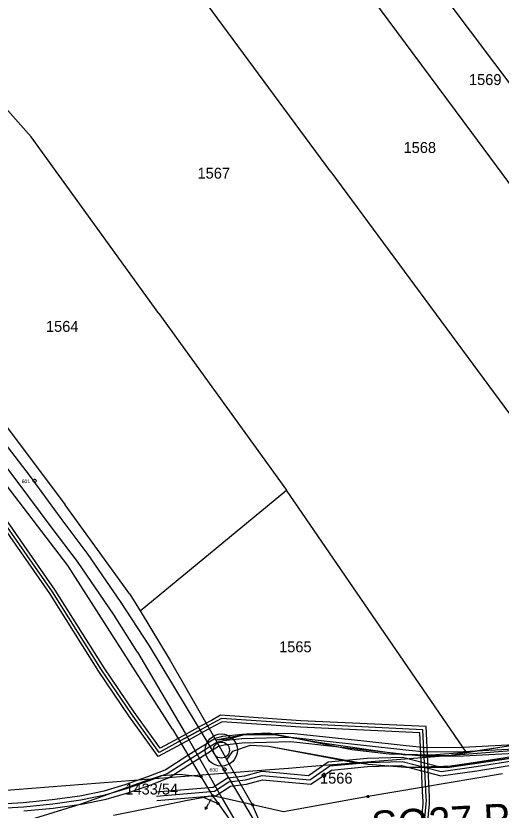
# Model space of a CAD drawing. Extents: x -510185 to -506993, y -1126306 to -1123642.
# Drawn here: x -509243.9 to -509017.3, y -1126120.6 to -1125749.7 of the extents above; entities that cross this region are included whole.
import ezdxf

# ---------------------------------------------------------------- set-up
doc = ezdxf.new("R2010")
doc.units = 0
for name, color, linetype in [('návrh', 7, 'Continuous'), ('ochranná pásma', 7, 'Continuous'), ('parcelni hranice', 7, 'Continuous'), ('telefonica', 7, 'Continuous'), ('u_kabely', 7, 'Continuous'), ('u_Telefonica', 7, 'Continuous'), ('u_Telematika', 7, 'Continuous'), ('u_teliasonera', 7, 'Continuous'), ('u_vysadba_oseti', 7, 'Continuous'), ('ˇ2', 7, 'Continuous'), ('ˇ3', 7, 'Continuous'), ('ˇ4', 7, 'Continuous'), ('ˇ7', 7, 'Continuous'), ('ˇ8', 7, 'Continuous')]:
    doc.layers.add(name, color=color, linetype=linetype)

msp = doc.modelspace()

# ---------------------------------------------------------------- linework, layer by layer
at = {"layer": 'návrh'}
for radius in [7.5, 3.75]:
    msp.add_circle((-509147.97, -1126092.6), radius, dxfattribs=at)
at = {"layer": 'ochranná pásma'}
for p, q in [((-509105.94, -1126100.2), (-508824.34, -1126077.96)), ((-509299.93, -1126115.29), (-509125.3, -1126101.71)), ((-509125.3, -1126101.71), (-509116.65, -1126101.04)), ((-509116.65, -1126101.04), (-509105.94, -1126100.2))]:
    msp.add_line(p, q, dxfattribs=at)
at = {"layer": 'parcelni hranice'}
for p, q in [((-509132.45, -1125667.17), (-509031.17, -1125804.26)), ((-509096.96, -1125670.04), (-508984.48, -1125819.86)), ((-509096.82, -1125822.54), (-509195.52, -1125688.71)), ((-509270.54, -1125768.18), (-509236.85, -1125806.19)), ((-509031.17, -1125804.26), (-508929.89, -1125941.34)), ((-509177.23, -1125888.69), (-509236.85, -1125806.19)), ((-509096.82, -1125822.54), (-508998.12, -1125956.36)), ((-509177.23, -1125888.69), (-509117.61, -1125971.19)), ((-509219.69, -1126006.46), (-509290.67, -1125913.76)), ((-509253.29, -1125935.06), (-509220.87, -1125978.05)), ((-509185.92, -1126027.53), (-509117.61, -1125971.19)), ((-509033.47, -1126093.73), (-509117.61, -1125971.19)), ((-509190.65, -1126019.76), (-509220.87, -1125978.05)), ((-509170.84, -1126082.86), (-509219.69, -1126006.46)), ((-509190.65, -1126019.76), (-509185.92, -1126027.53)), ((-509185.92, -1126027.53), (-509171.81, -1126050.71)), ((-509171.81, -1126050.71), (-509150.59, -1126088)), ((-509170.84, -1126082.86), (-509157.49, -1126104.93)), ((-509144.61, -1126087.44), (-509150.59, -1126088)), ((-509136.24, -1126085.24), (-509144.61, -1126087.44)), ((-509125.75, -1126084.77), (-509136.24, -1126085.24)), ((-509087.06, -1126092.49), (-509125.75, -1126084.77)), ((-509150.59, -1126088), (-509145.35, -1126097.2)), ((-509142.58, -1126093.06), (-509134.29, -1126090.27)), ((-509134.29, -1126090.27), (-509125.88, -1126090.73)), ((-509125.88, -1126090.73), (-509088.21, -1126097.98)), ((-509000.11, -1126088.82), (-509033.47, -1126093.73)), ((-509145.35, -1126097.2), (-509142.58, -1126093.06)), ((-509069.53, -1126094.45), (-509087.06, -1126092.49)), ((-509049.74, -1126094.93), (-509069.53, -1126094.45)), ((-509033.47, -1126093.73), (-509049.74, -1126094.93)), ((-509133.41, -1126118.18), (-509145.35, -1126097.2)), ((-509088.21, -1126097.98), (-509079.38, -1126099.22)), ((-509038.29, -1126099.96), (-509009.46, -1126095.8)), ((-509079.38, -1126099.22), (-509061.84, -1126100.54)), ((-509061.84, -1126100.54), (-509038.29, -1126099.96)), ((-509184.36, -1126107.35), (-509175.99, -1126104.45)), ((-509175.99, -1126104.45), (-509167.34, -1126103.9)), ((-509167.34, -1126103.9), (-509157.49, -1126104.93)), ((-509157.49, -1126104.93), (-509152.05, -1126113.93)), ((-509016.64, -1126103.65), (-509079.41, -1126114.29)), ((-509213.38, -1126117.64), (-509184.36, -1126107.35)), ((-509164.5, -1126116.32), (-509180.44, -1126119.53)), ((-509156.22, -1126114.73), (-509164.5, -1126116.32)), ((-509152.05, -1126113.93), (-509156.22, -1126114.73)), ((-509156.22, -1126114.73), (-509149.48, -1126117.53)), ((-509152.05, -1126113.93), (-509149.48, -1126117.53)), ((-509147.69, -1126114.92), (-509152.05, -1126113.93)), ((-509137.41, -1126117.27), (-509147.69, -1126114.92)), ((-509079.41, -1126114.29), (-509118.98, -1126121.47)), ((-509248.18, -1126128.53), (-509213.38, -1126117.64)), ((-509180.44, -1126119.53), (-509198.31, -1126123.18)), ((-509149.48, -1126117.53), (-509131.41, -1126142.82)), ((-509133.41, -1126118.18), (-509137.41, -1126117.27)), ((-509123.08, -1126141.76), (-509133.41, -1126118.18)), ((-509118.98, -1126121.47), (-509133.41, -1126118.18))]:
    msp.add_line(p, q, dxfattribs=at)
at = {"layer": 'telefonica'}
for points in [[(-509188.65, -1126074.91), (-509202.69, -1126054.24), (-509225.62, -1126017.86), (-509249.3, -1125983.88), (-509275.16, -1125949.5), (-509300.47, -1125915.43), (-509336.7, -1125871.25)], [(-509191.13, -1126076.6), (-509205.2, -1126055.89), (-509228.12, -1126019.51), (-509251.73, -1125985.64), (-509277.57, -1125951.3), (-509302.83, -1125917.28), (-509339.02, -1125873.16)], [(-509152.64, -1126078.73), (-509157.74, -1126081.5), (-509165.82, -1126085.91), (-509176.52, -1126091.75), (-509188.68, -1126074.88)], [(-509110.81, -1126078.92), (-509148.31, -1126076.36), (-509152.64, -1126078.73)], [(-509151.21, -1126081.36), (-509156.3, -1126084.14), (-509164.39, -1126088.55), (-509177.41, -1126095.65), (-509191.11, -1126076.63)], [(-509111.02, -1126081.92), (-509147.64, -1126079.41), (-509151.21, -1126081.36)], [(-509035.07, -1126146.08), (-509047.88, -1126145.88), (-509052.14, -1126132.19), (-509050.74, -1126117.76), (-509050.68, -1126116.1), (-509050.8, -1126114.54), (-509052.36, -1126081.64), (-509110.85, -1126078.92)], [(-509037.56, -1126149.04), (-509050.1, -1126148.85), (-509055.18, -1126132.5), (-509053.73, -1126117.56), (-509053.69, -1126116.16), (-509053.79, -1126114.72), (-509055.23, -1126084.51), (-509110.99, -1126081.92)]]:
    msp.add_lwpolyline(points, dxfattribs=at)
at = {"layer": 'u_kabely'}
for points in [[(-509264.3, -1126118.51), (-509240.59, -1126117.08), (-509226.95, -1126115.72), (-509214, -1126113.93), (-509202.75, -1126111.6), (-509192.89, -1126108.72), (-509181.81, -1126104.87), (-509174.17, -1126101.82), (-509163.64, -1126095.05), (-509159.85, -1126092.67), (-509154.66, -1126089.4), (-509150.89, -1126087.02), (-509147.31, -1126086.16), (-509138.48, -1126085.2), (-509115.38, -1126084.64), (-509081.38, -1126088.3), (-509061.66, -1126090.49), (-509052.49, -1126091.41), (-509034.97, -1126091.24), (-509005.3, -1126089.75)], [(-509240.27, -1126121.06), (-509226.47, -1126119.7), (-509213.32, -1126117.87), (-509201.79, -1126115.48), (-509191.67, -1126112.54), (-509180.41, -1126108.61), (-509172.33, -1126105.4), (-509161.5, -1126098.43), (-509157.72, -1126096.05), (-509152.53, -1126092.78), (-509149.31, -1126090.76), (-509146.63, -1126090.1), (-509138.22, -1126089.2), (-509115.54, -1126088.64), (-509081.82, -1126092.28), (-509062.08, -1126094.47), (-509052.67, -1126095.41), (-509034.85, -1126095.24), (-509005.08, -1126093.75)]]:
    msp.add_lwpolyline(points, dxfattribs=at)
at = {"layer": 'u_Telefonica'}
msp.add_line((-509165.11, -1126087.23), (-509157.02, -1126082.82), dxfattribs=at)
msp.add_line((-509165.11, -1126087.23), (-509157.02, -1126082.82), dxfattribs=at)
for points in [[(-509189.89, -1126075.76), (-509203.95, -1126055.06), (-509226.87, -1126018.69), (-509250.52, -1125984.76), (-509276.37, -1125950.4), (-509301.65, -1125916.36), (-509337.86, -1125872.21)], [(-509189.89, -1126075.76), (-509203.95, -1126055.06), (-509226.87, -1126018.69), (-509250.52, -1125984.76), (-509276.37, -1125950.4), (-509301.65, -1125916.36), (-509337.86, -1125872.21)], [(-509151.93, -1126080.04), (-509157.02, -1126082.82), (-509165.11, -1126087.23), (-509176.97, -1126093.7), (-509189.89, -1126075.76)], [(-509151.93, -1126080.04), (-509157.02, -1126082.82), (-509165.11, -1126087.23), (-509176.97, -1126093.7), (-509189.89, -1126075.76)], [(-509110.92, -1126080.42), (-509147.97, -1126077.89), (-509151.93, -1126080.04)], [(-509110.92, -1126080.42), (-509147.97, -1126077.89), (-509151.93, -1126080.04)], [(-509036.23, -1126147.56), (-509048.99, -1126147.36), (-509053.66, -1126132.34), (-509052.23, -1126117.66), (-509052.19, -1126116.13), (-509052.3, -1126114.63), (-509053.79, -1126083.08), (-509110.92, -1126080.42)], [(-509036.23, -1126147.56), (-509048.99, -1126147.36), (-509053.66, -1126132.34), (-509052.23, -1126117.66), (-509052.19, -1126116.13), (-509052.3, -1126114.63), (-509053.79, -1126083.08), (-509110.92, -1126080.42)]]:
    msp.add_lwpolyline(points, dxfattribs=at)
at = {"layer": 'u_Telematika'}
for points in [[(-509178.48, -1126112.16), (-509151.77, -1126109.86), (-509145.12, -1126105.54), (-509137.05, -1126104.59), (-509129.09, -1126102.42), (-509107.22, -1126104.44), (-509098.01, -1126098.09), (-509079.9, -1126096.35), (-509063.3, -1126095.88), (-509045.18, -1126100.63), (-509029.24, -1126098.3), (-509009.45, -1126095.13), (-508979.67, -1126089.87), (-508962.19, -1126088.98), (-508958.38, -1126086.54), (-508857.97, -1126081.38), (-508783.2, -1126074.98), (-508758.1, -1126074.61), (-508714.17, -1126073.15), (-508610.79, -1126061.9), (-508536.04, -1126055.5)], [(-509178.3, -1126114.15), (-509151.1, -1126111.81), (-509144.42, -1126107.47), (-509136.67, -1126106.56), (-509128.91, -1126104.44), (-509106.68, -1126106.5), (-509097.3, -1126100.03), (-509079.77, -1126098.34), (-509063.53, -1126097.88), (-509045.3, -1126102.67), (-509028.93, -1126100.27), (-509009.12, -1126097.11), (-508979.44, -1126091.86), (-508961.56, -1126090.95), (-508957.75, -1126088.51), (-508857.83, -1126083.37), (-508783.1, -1126076.98), (-508758.05, -1126076.61), (-508714.03, -1126075.15), (-508610.6, -1126063.89), (-508535.87, -1126057.49)], [(-509178.13, -1126116.15), (-509150.43, -1126113.76), (-509143.73, -1126109.4), (-509136.29, -1126108.53), (-509128.74, -1126106.47), (-509106.14, -1126108.56), (-509096.6, -1126101.97), (-509079.65, -1126100.34), (-509063.76, -1126099.89), (-509045.41, -1126104.7), (-509028.63, -1126102.25), (-509008.79, -1126099.08), (-508979.22, -1126093.85), (-508960.92, -1126092.92), (-508957.12, -1126090.48), (-508857.69, -1126085.37), (-508783, -1126078.98), (-508758.01, -1126078.61), (-508713.89, -1126077.15), (-508610.4, -1126065.88), (-508535.7, -1126059.49)]]:
    msp.add_lwpolyline(points, dxfattribs=at)
at = {"layer": 'u_teliasonera'}
msp.add_lwpolyline([(-509264.2, -1126120.51), (-509240.43, -1126119.07), (-509226.71, -1126117.71), (-509213.66, -1126115.9), (-509202.27, -1126113.54), (-509192.28, -1126110.63), (-509181.11, -1126106.74), (-509173.25, -1126103.61), (-509162.57, -1126096.74), (-509158.79, -1126094.36), (-509153.6, -1126091.09), (-509150.1, -1126088.89), (-509146.97, -1126088.13), (-509138.35, -1126087.2), (-509115.46, -1126086.64), (-509081.6, -1126090.29), (-509061.87, -1126092.48), (-509052.58, -1126093.41), (-509034.91, -1126093.24), (-509005.19, -1126091.75)], dxfattribs=at)
at = {"layer": 'u_vysadba_oseti'}
msp.add_lwpolyline([(-508970.77, -1126083.85), (-509041.89, -1126095.35), (-509063.11, -1126094.87), (-509100.69, -1126089.36), (-509123.38, -1126085.47), (-509138.12, -1126085.63), (-509150.59, -1126088), (-509145.35, -1126097.2), (-509142.58, -1126093.06), (-509134.29, -1126090.27), (-509125.88, -1126090.73), (-509079.38, -1126099.22), (-509061.84, -1126100.54), (-509042.54, -1126100.7), (-508993.61, -1126093.57)], dxfattribs=at)
at = {"layer": 'ˇ3'}
msp.add_lwpolyline([(-509101.06, -1126104.48), (-509099.06, -1126104.48)], dxfattribs=at)
msp.add_lwpolyline([(-509100.56, -1126103.98), (-509100.47, -1126103.69), (-509100.22, -1126103.5), (-509099.91, -1126103.5), (-509099.66, -1126103.69), (-509099.56, -1126103.98), (-509099.56, -1126104.98), (-509099.66, -1126105.27), (-509099.91, -1126105.46), (-509100.22, -1126105.46), (-509100.47, -1126105.27), (-509100.56, -1126104.98)], close=True, dxfattribs=at)
at = {"layer": 'ˇ4'}
for p, q in [((-509237.56, -1125964.26), (-509264.86, -1125928.78)), ((-509242.83, -1125967.72), (-509269.67, -1125932.73)), ((-509222.8, -1125984.39), (-509237.56, -1125964.26)), ((-509227.52, -1125988.32), (-509242.83, -1125967.72)), ((-509210.17, -1126001.33), (-509222.8, -1125984.39)), ((-509215.11, -1126004.61), (-509227.52, -1125988.32)), ((-509195.09, -1126023.22), (-509210.17, -1126001.33)), ((-509198.38, -1126029.08), (-509215.11, -1126004.61)), ((-509181.53, -1126044), (-509195.09, -1126023.22)), ((-509187.2, -1126046.9), (-509198.38, -1126029.08)), ((-509158.84, -1126081.6), (-509181.53, -1126044)), ((-509187.2, -1126046.9), (-509164.85, -1126084.71)), ((-509137.41, -1126117.27), (-509158.84, -1126081.6)), ((-509164.85, -1126084.71), (-509147.69, -1126114.92)), ((-509147.69, -1126114.92), (-509131.41, -1126142.82)), ((-509123.08, -1126141.76), (-509137.41, -1126117.27))]:
    msp.add_line(p, q, dxfattribs=at)
at = {"layer": 'ˇ7'}
msp.add_line((-509152.86, -1126115.48), (-509154.01, -1126117.65), dxfattribs=at)
for points in [[(-509155.42, -1126120.3), (-509154.01, -1126117.65)], [(-509154.51, -1126119.65), (-509155.42, -1126120.3), (-509155.39, -1126119.18)]]:
    msp.add_lwpolyline(points, dxfattribs=at)
at = {"layer": 'ˇ8'}
for points in [[(-509234.92, -1125966.16), (-509234.58, -1125966.35), (-509234.39, -1125966.69), (-509234.39, -1125967.07), (-509234.58, -1125967.41), (-509234.92, -1125967.6), (-509235.3, -1125967.6), (-509235.64, -1125967.41), (-509235.83, -1125967.07), (-509235.83, -1125966.69), (-509235.64, -1125966.35), (-509235.3, -1125966.16)], [(-509146.29, -1126100.96), (-509145.95, -1126101.15), (-509145.76, -1126101.49), (-509145.76, -1126101.87), (-509145.95, -1126102.21), (-509146.29, -1126102.4), (-509146.67, -1126102.4), (-509147.01, -1126102.21), (-509147.2, -1126101.87), (-509147.2, -1126101.49), (-509147.01, -1126101.15), (-509146.67, -1126100.96)], [(-509157.34, -1126104.45), (-509157.09, -1126104.64), (-509156.99, -1126104.93), (-509157.09, -1126105.22), (-509157.34, -1126105.41), (-509157.64, -1126105.41), (-509157.89, -1126105.22), (-509157.99, -1126104.93), (-509157.89, -1126104.64), (-509157.64, -1126104.45)], [(-509151.9, -1126113.45), (-509151.65, -1126113.64), (-509151.55, -1126113.93), (-509151.65, -1126114.22), (-509151.9, -1126114.41), (-509152.2, -1126114.41), (-509152.45, -1126114.22), (-509152.55, -1126113.93), (-509152.45, -1126113.64), (-509152.2, -1126113.45)], [(-509149.33, -1126117.05), (-509149.08, -1126117.24), (-509148.98, -1126117.53), (-509149.08, -1126117.82), (-509149.33, -1126118.01), (-509149.63, -1126118.01), (-509149.88, -1126117.82), (-509149.98, -1126117.53), (-509149.88, -1126117.24), (-509149.63, -1126117.05)], [(-509079.26, -1126113.81), (-509079.01, -1126114), (-509078.91, -1126114.29), (-509079.01, -1126114.58), (-509079.26, -1126114.77), (-509079.56, -1126114.77), (-509079.81, -1126114.58), (-509079.91, -1126114.29), (-509079.81, -1126114), (-509079.56, -1126113.81)], [(-509133.26, -1126117.7), (-509133.01, -1126117.89), (-509132.91, -1126118.18), (-509133.01, -1126118.47), (-509133.26, -1126118.66), (-509133.56, -1126118.66), (-509133.81, -1126118.47), (-509133.91, -1126118.18), (-509133.81, -1126117.89), (-509133.56, -1126117.7)]]:
    msp.add_lwpolyline(points, close=True, dxfattribs=at)
for points in [[(-509235.16, -1125966.88), (-509235.06, -1125966.88)], [(-509146.53, -1126101.68), (-509146.43, -1126101.68)], [(-509157.61, -1126104.93), (-509157.37, -1126104.93)], [(-509152.17, -1126113.93), (-509151.93, -1126113.93)], [(-509079.53, -1126114.29), (-509079.29, -1126114.29)], [(-509149.6, -1126117.53), (-509149.36, -1126117.53)], [(-509133.53, -1126118.18), (-509133.29, -1126118.18)]]:
    msp.add_lwpolyline(points, dxfattribs=at)

# ---------------------------------------------------------------- texts
at = {"layer": 'u_vysadba_oseti'}
msp.add_text('SO27 Polní cesta PC 45a - dl. 625 m', height=13.875, rotation=3.3298, dxfattribs=at).set_placement((-509077.56, -1126135.03))
at = {"layer": 'ˇ2'}
for s, height, p in [('1569', 5.1, (-509032.31, -1125782.03)), ('1568', 5.1, (-509062.87, -1125813.76)), ('1567', 5.1, (-509159.1, -1125825.74)), ('1564', 5.1, (-509229.88, -1125897.3)), ('1565', 5.1, (-509120.99, -1126046.92)), ('1566', 5.1, (-509101.87, -1126108.28)), ('1433/54', 5.1, (-509192.8, -1126113.37)), ('1433/55', 0.3, (-509152.84, -1126115.48))]:
    msp.add_text(s, height=height, dxfattribs=at).set_placement(p)
at = {"layer": 'ˇ8'}
for s, p in [('601', (-509241.22, -1125967.96)), ('600', (-509153.5, -1126102.76))]:
    msp.add_text(s, height=1.7, dxfattribs=at).set_placement(p)

doc.saveas('drawing.dxf')
